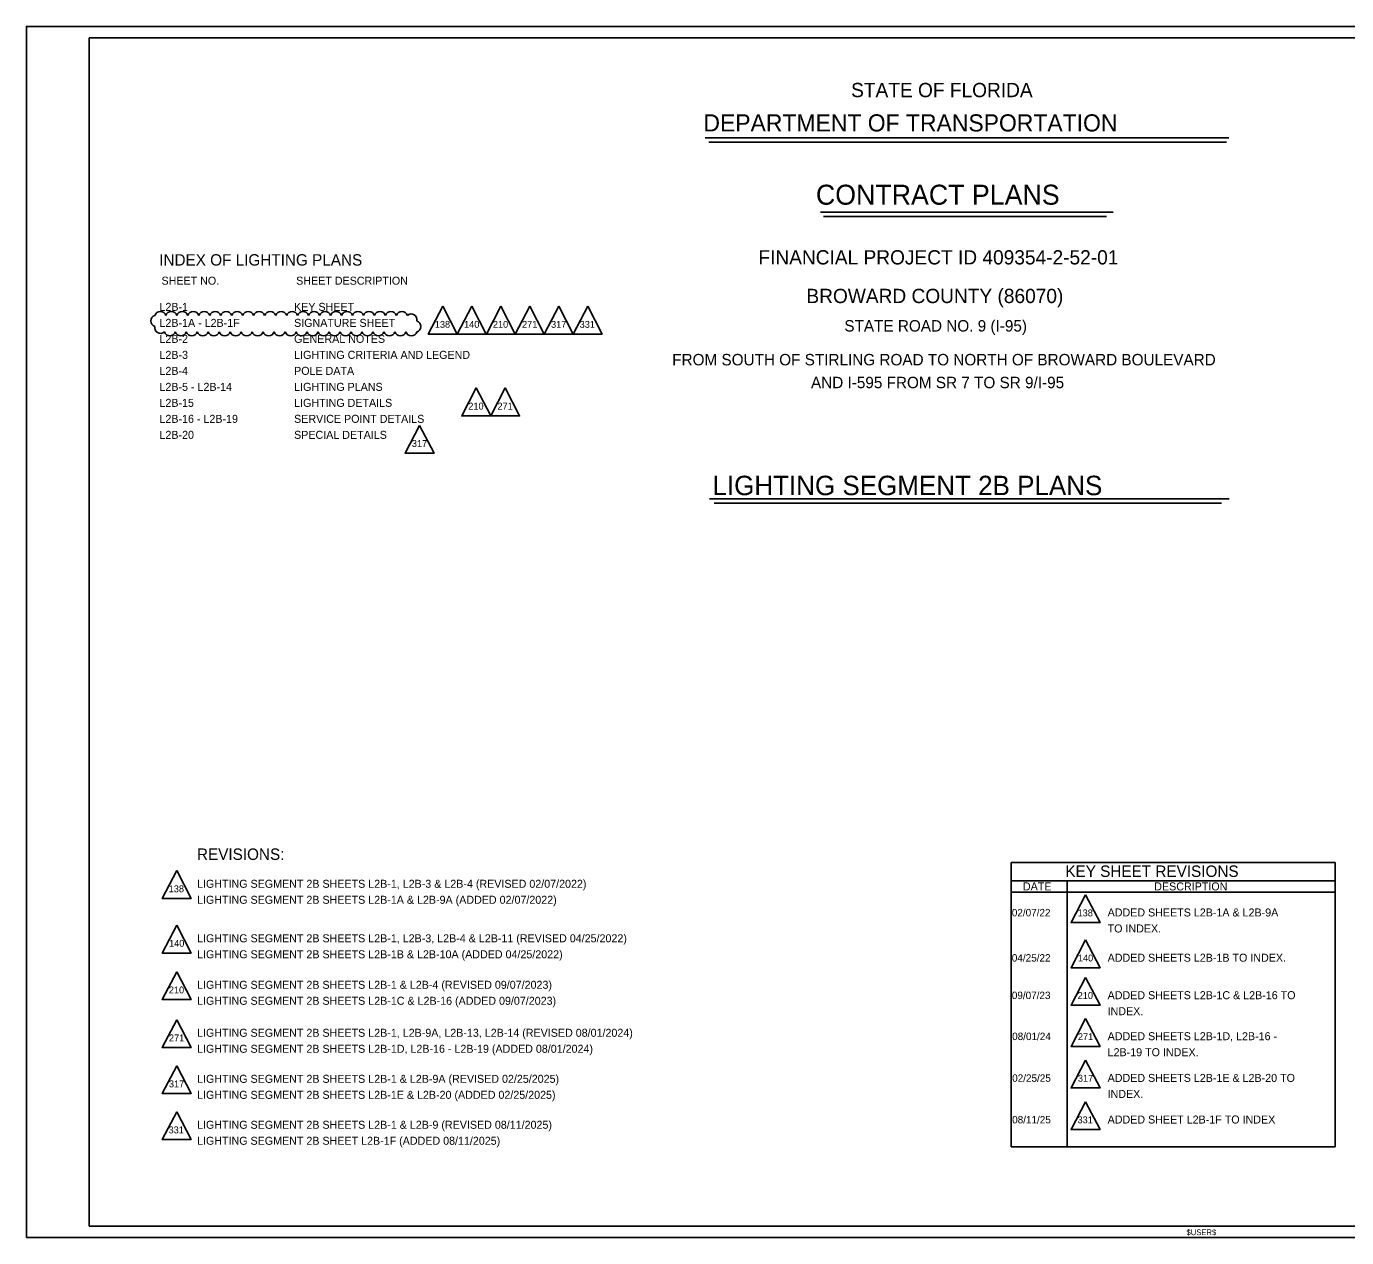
# Model space of a CAD drawing. Extents: x -820.2 to -798.1, y -2199.1 to -2188.5.
# Drawn here: x -820.23 to -808.68, y -2199.12 to -2188.52 of the extents above; entities that cross this region are included whole.
import ezdxf

# ---------------------------------------------------------------- set-up
doc = ezdxf.new("R2010")
doc.units = 0
for name, color, linetype in [('AdhocPoint_dp', 7, 'Continuous'), ('Cloud_dp', 7, 'Continuous'), ('PlotBorder_dp', 7, 'Continuous'), ('SheetBorder_dp', 7, 'Continuous'), ('SumBoxLines_dp', 7, 'Continuous'), ('TextLabel', 7, 'Continuous'), ('TextMinor', 7, 'Continuous'), ('TextNotes', 7, 'Continuous'), ('TextTitle', 7, 'Continuous')]:
    doc.layers.add(name, color=color, linetype=linetype)

msp = doc.modelspace()

# ---------------------------------------------------------------- linework, layer by layer
at = {"layer": 'AdhocPoint_dp'}
msp.add_line((-820.227, -2199.124), (-820.227, -2199.124), dxfattribs=at)
at = {"layer": 'Cloud_dp'}
for points in [[(-816.585, -2190.972), (-816.711, -2191.216), (-816.458, -2191.216)], [(-816.331, -2190.972), (-816.458, -2191.216), (-816.204, -2191.216)], [(-816.077, -2190.972), (-816.203, -2191.216), (-815.95, -2191.216)], [(-815.823, -2190.972), (-815.95, -2191.216), (-815.696, -2191.216)], [(-815.57, -2190.972), (-815.696, -2191.216), (-815.443, -2191.216)], [(-815.316, -2190.972), (-815.443, -2191.216), (-815.19, -2191.216)], [(-816.292, -2191.688), (-816.419, -2191.932), (-816.165, -2191.932)], [(-816.038, -2191.688), (-816.165, -2191.932), (-815.912, -2191.932)], [(-816.787, -2192.015), (-816.914, -2192.259), (-816.661, -2192.259)], [(-818.912, -2195.912), (-819.039, -2196.156), (-818.786, -2196.156)], [(-810.961, -2196.123), (-811.088, -2196.367), (-810.834, -2196.367)], [(-818.912, -2196.389), (-819.039, -2196.633), (-818.786, -2196.633)], [(-810.961, -2196.518), (-811.088, -2196.762), (-810.834, -2196.762)], [(-818.912, -2196.797), (-819.039, -2197.041), (-818.786, -2197.041)], [(-810.961, -2196.846), (-811.088, -2197.09), (-810.834, -2197.09)], [(-818.912, -2197.217), (-819.039, -2197.461), (-818.786, -2197.461)], [(-810.961, -2197.205), (-811.088, -2197.45), (-810.834, -2197.45)], [(-818.912, -2197.619), (-819.039, -2197.863), (-818.786, -2197.863)], [(-810.961, -2197.57), (-811.088, -2197.814), (-810.834, -2197.814)], [(-810.961, -2197.934), (-811.088, -2198.178), (-810.834, -2198.178)], [(-818.912, -2198.022), (-819.039, -2198.266), (-818.786, -2198.266)]]:
    msp.add_lwpolyline(points, close=True, dxfattribs=at)
for centre, radius, start, end in [((-819.088, -2191.101), 0.0504, 107.5, 252.5), ((-819.055, -2191.068), 0.0504, 17.5, 162.5), ((-818.959, -2191.068), 0.0504, 17.5, 162.5), ((-818.863, -2191.068), 0.0504, 17.5, 162.5), ((-818.767, -2191.068), 0.0504, 17.5, 162.5), ((-818.671, -2191.068), 0.0504, 17.5, 162.5), ((-818.575, -2191.068), 0.0504, 17.5, 162.5), ((-818.479, -2191.068), 0.0504, 17.5, 162.5), ((-818.383, -2191.068), 0.0504, 17.5, 162.5), ((-818.287, -2191.068), 0.0504, 17.5, 162.5), ((-818.191, -2191.068), 0.0504, 17.5, 162.5), ((-818.094, -2191.068), 0.0504, 17.5, 162.5), ((-817.998, -2191.068), 0.0504, 17.5, 162.5), ((-817.902, -2191.068), 0.0504, 17.5, 162.5), ((-817.806, -2191.068), 0.0504, 17.5, 162.5), ((-817.71, -2191.068), 0.0504, 17.5, 162.5), ((-817.614, -2191.068), 0.0504, 17.5, 162.5), ((-817.518, -2191.068), 0.0504, 17.5, 162.5), ((-817.422, -2191.068), 0.0504, 17.5, 162.5), ((-817.326, -2191.068), 0.0504, 17.5, 162.5), ((-817.23, -2191.068), 0.0504, 17.5, 162.5), ((-817.134, -2191.068), 0.0504, 17.5, 162.5), ((-817.038, -2191.068), 0.0504, 17.5, 162.5), ((-816.942, -2191.068), 0.0504, 17.5, 162.5), ((-816.86, -2191.09), 0.0503, 347.2695, 132.2695), ((-819.054, -2191.16), 0.0503, 167.2695, 312.2695), ((-816.826, -2191.15), 0.0504, 287.5, 72.5), ((-818.972, -2191.182), 0.0504, 197.5, 342.5), ((-818.876, -2191.182), 0.0504, 197.5, 342.5), ((-818.78, -2191.182), 0.0504, 197.5, 342.5), ((-818.684, -2191.182), 0.0504, 197.5, 342.5), ((-818.588, -2191.182), 0.0504, 197.5, 342.5), ((-818.492, -2191.182), 0.0504, 197.5, 342.5), ((-818.396, -2191.182), 0.0504, 197.5, 342.5), ((-818.3, -2191.182), 0.0504, 197.5, 342.5), ((-818.204, -2191.182), 0.0504, 197.5, 342.5), ((-818.108, -2191.182), 0.0504, 197.5, 342.5), ((-818.012, -2191.182), 0.0504, 197.5, 342.5), ((-817.915, -2191.182), 0.0504, 197.5, 342.5), ((-817.819, -2191.182), 0.0504, 197.5, 342.5), ((-817.723, -2191.182), 0.0504, 197.5, 342.5), ((-817.627, -2191.182), 0.0504, 197.5, 342.5), ((-817.531, -2191.182), 0.0504, 197.5, 342.5), ((-817.435, -2191.182), 0.0504, 197.5, 342.5), ((-817.339, -2191.182), 0.0504, 197.5, 342.5), ((-817.243, -2191.182), 0.0504, 197.5, 342.5), ((-817.147, -2191.182), 0.0504, 197.5, 342.5), ((-817.051, -2191.182), 0.0504, 197.5, 342.5), ((-816.955, -2191.182), 0.0504, 197.5, 342.5), ((-816.859, -2191.182), 0.0504, 197.5, 342.5)]:
    msp.add_arc(centre, radius, start, end, dxfattribs=at)
at = {"layer": 'PlotBorder_dp'}
msp.add_lwpolyline([(-820.227, -2199.124), (-803.727, -2199.124), (-803.727, -2188.524), (-820.227, -2188.524)], close=True, dxfattribs=at)
at = {"layer": 'SheetBorder_dp'}
for p, q in [((-819.677, -2188.624), (-819.677, -2199.024)), ((-819.677, -2188.624), (-804.277, -2188.624)), ((-819.677, -2199.024), (-804.277, -2199.024))]:
    msp.add_line(p, q, dxfattribs=at)
at = {"layer": 'SumBoxLines_dp'}
for p, q in [((-811.612, -2195.84), (-811.612, -2198.329)), ((-811.612, -2195.84), (-808.777, -2195.84)), ((-808.777, -2195.84), (-808.777, -2198.329)), ((-811.612, -2196), (-808.777, -2196)), ((-811.122, -2196), (-811.122, -2198.329)), ((-811.612, -2196.1), (-808.777, -2196.1)), ((-811.612, -2198.329), (-808.777, -2198.329))]:
    msp.add_line(p, q, dxfattribs=at)
at = {"layer": 'TextTitle'}
for p, q in [((-814.289, -2189.5), (-809.707, -2189.5)), ((-814.257, -2189.538), (-809.729, -2189.538)), ((-813.281, -2190.15), (-810.719, -2190.15)), ((-813.253, -2190.188), (-810.777, -2190.188)), ((-814.252, -2192.659), (-809.704, -2192.659)), ((-814.209, -2192.697), (-809.772, -2192.697))]:
    msp.add_line(p, q, dxfattribs=at)

# ---------------------------------------------------------------- texts
at = {"layer": 'Cloud_dp'}
for s, p in [('138', (-816.654, -2191.161)), ('140', (-816.398, -2191.161)), ('210', (-816.146, -2191.161)), ('271', (-815.891, -2191.161)), ('317', (-815.637, -2191.161)), ('331', (-815.387, -2191.161)), ('210', (-816.361, -2191.877)), ('271', (-816.106, -2191.877)), ('317', (-816.855, -2192.204)), ('138', (-818.982, -2196.101)), ('138', (-811.031, -2196.312)), ('140', (-818.979, -2196.578)), ('140', (-811.028, -2196.707)), ('210', (-818.981, -2196.986)), ('210', (-811.03, -2197.035)), ('271', (-818.98, -2197.406)), ('271', (-811.028, -2197.395)), ('317', (-818.98, -2197.808)), ('317', (-811.028, -2197.759)), ('331', (-811.031, -2198.123)), ('331', (-818.983, -2198.211))]:
    msp.add_text(s, height=0.06, rotation=0, dxfattribs=at).set_placement(p)
at = {"layer": 'TextLabel'}
for s, height, p in [('FINANCIAL PROJECT ID 409354-2-52-01', 0.125, (-813.823, -2190.607)), ('INDEX OF LIGHTING PLANS', 0.1, (-819.065, -2190.617)), ('BROWARD COUNTY (86070)', 0.125, (-813.403, -2190.945)), ('L2B-1', 0.07, (-819.063, -2191.013)), ('KEY SHEET', 0.07, (-817.885, -2191.013)), ('L2B-1A - L2B-1F', 0.07, (-819.063, -2191.153)), ('SIGNATURE SHEET', 0.07, (-817.885, -2191.153)), ('STATE ROAD NO. 9 (I-95)', 0.1, (-813.071, -2191.194)), ('L2B-2', 0.07, (-819.063, -2191.293)), ('GENERAL NOTES', 0.07, (-817.885, -2191.293)), ('L2B-3', 0.07, (-819.063, -2191.433)), ('LIGHTING CRITERIA AND LEGEND', 0.07, (-817.885, -2191.433)), ('FROM SOUTH OF STIRLING ROAD TO NORTH OF BROWARD BOULEVARD', 0.1, (-814.577, -2191.49)), ('L2B-4', 0.07, (-819.063, -2191.573)), ('POLE DATA', 0.07, (-817.885, -2191.573)), ('L2B-5 - L2B-14', 0.07, (-819.063, -2191.713)), ('LIGHTING PLANS', 0.07, (-817.885, -2191.713)), ('AND I-595 FROM SR 7 TO SR 9/I-95', 0.1, (-813.363, -2191.69)), ('L2B-15', 0.07, (-819.063, -2191.853)), ('LIGHTING DETAILS', 0.07, (-817.885, -2191.853)), ('L2B-16 - L2B-19', 0.07, (-819.063, -2191.993)), ('SERVICE POINT DETAILS', 0.07, (-817.885, -2191.993)), ('L2B-20', 0.07, (-819.063, -2192.133)), ('SPECIAL DETAILS', 0.07, (-817.885, -2192.133)), ('REVISIONS:', 0.1, (-818.735, -2195.818)), ('KEY SHEET REVISIONS', 0.1, (-811.138, -2195.967))]:
    msp.add_text(s, height=height, dxfattribs=at).set_placement(p)
at = {"layer": 'TextMinor'}
for s, height, p in [('02/07/22', 0.065, (-811.606, -2196.312)), ('ADDED SHEETS L2B-1A & L2B-9A ', 0.07, (-810.768, -2196.313)), ('TO INDEX.', 0.07, (-810.768, -2196.453)), ('04/25/22', 0.065, (-811.606, -2196.708)), ('ADDED SHEETS L2B-1B TO INDEX.', 0.07, (-810.768, -2196.709)), ('09/07/23', 0.065, (-811.606, -2197.036)), ('ADDED SHEETS L2B-1C & L2B-16 TO ', 0.07, (-810.768, -2197.037)), ('INDEX.', 0.07, (-810.768, -2197.177)), ('08/01/24', 0.065, (-811.603, -2197.395)), ('ADDED SHEETS L2B-1D, L2B-16 - ', 0.07, (-810.768, -2197.396)), ('L2B-19 TO INDEX.', 0.07, (-810.768, -2197.536)), ('02/25/25', 0.065, (-811.603, -2197.76)), ('ADDED SHEETS L2B-1E & L2B-20 TO ', 0.07, (-810.768, -2197.761)), ('INDEX.', 0.07, (-810.768, -2197.901)), ('08/11/25', 0.065, (-811.603, -2198.124)), ('ADDED SHEET L2B-1F TO INDEX', 0.07, (-810.768, -2198.125)), ('$USER$', 0.05, (-810.078, -2199.102))]:
    msp.add_text(s, height=height, dxfattribs=at).set_placement(p)
at = {"layer": 'TextNotes'}
for s, height, p in [('SHEET NO.', 0.07, (-819.045, -2190.784)), ('SHEET DESCRIPTION', 0.07, (-817.867, -2190.784)), ('LIGHTING SEGMENT 2B SHEETS L2B-1, L2B-3 & L2B-4 (REVISED 02/07/2022)', 0.06998, (-818.734, -2196.062)), ('DATE', 0.07, (-811.509, -2196.085)), ('DESCRIPTION', 0.07, (-810.36, -2196.085)), ('LIGHTING SEGMENT 2B SHEETS L2B-1A & L2B-9A (ADDED 02/07/2022)', 0.06998, (-818.734, -2196.202)), ('LIGHTING SEGMENT 2B SHEETS L2B-1, L2B-3, L2B-4 & L2B-11 (REVISED 04/25/2022)', 0.06998, (-818.734, -2196.539)), ('LIGHTING SEGMENT 2B SHEETS L2B-1B & L2B-10A (ADDED 04/25/2022)', 0.06998, (-818.734, -2196.679)), ('LIGHTING SEGMENT 2B SHEETS L2B-1 & L2B-4 (REVISED 09/07/2023)', 0.06998, (-818.734, -2196.946)), ('LIGHTING SEGMENT 2B SHEETS L2B-1C & L2B-16 (ADDED 09/07/2023)', 0.06998, (-818.734, -2197.086)), ('LIGHTING SEGMENT 2B SHEETS L2B-1, L2B-9A, L2B-13, L2B-14 (REVISED 08/01/2024)', 0.06998, (-818.734, -2197.366)), ('LIGHTING SEGMENT 2B SHEETS L2B-1D, L2B-16 - L2B-19 (ADDED 08/01/2024)', 0.06998, (-818.734, -2197.506)), ('LIGHTING SEGMENT 2B SHEETS L2B-1 & L2B-9A (REVISED 02/25/2025)', 0.06998, (-818.734, -2197.769)), ('LIGHTING SEGMENT 2B SHEETS L2B-1E & L2B-20 (ADDED 02/25/2025)', 0.06998, (-818.734, -2197.909)), ('LIGHTING SEGMENT 2B SHEETS L2B-1 & L2B-9 (REVISED 08/11/2025)', 0.06998, (-818.734, -2198.171)), ('LIGHTING SEGMENT 2B SHEET L2B-1F (ADDED 08/11/2025)', 0.06998, (-818.734, -2198.311))]:
    msp.add_text(s, height=height, dxfattribs=at).set_placement(p)
at = {"layer": 'TextTitle'}
for s, height, p in [('STATE OF FLORIDA', 0.125, (-813.012, -2189.143)), ('DEPARTMENT OF TRANSPORTATION', 0.15, (-814.304, -2189.443)), ('CONTRACT PLANS', 0.175, (-813.32, -2190.084)), ('LIGHTING SEGMENT 2B PLANS', 0.17, (-814.225, -2192.626))]:
    msp.add_text(s, height=height, dxfattribs=at).set_placement(p)

doc.saveas('drawing.dxf')
